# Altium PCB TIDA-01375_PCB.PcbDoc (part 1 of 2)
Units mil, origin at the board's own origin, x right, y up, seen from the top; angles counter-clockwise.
Board outline 3937.01 x 3149.61 mil, 2 copper layers (Top Layer, Bottom Layer), stack 62 mil thick; 52 components, 33 nets, 136 pads, 897 vias.
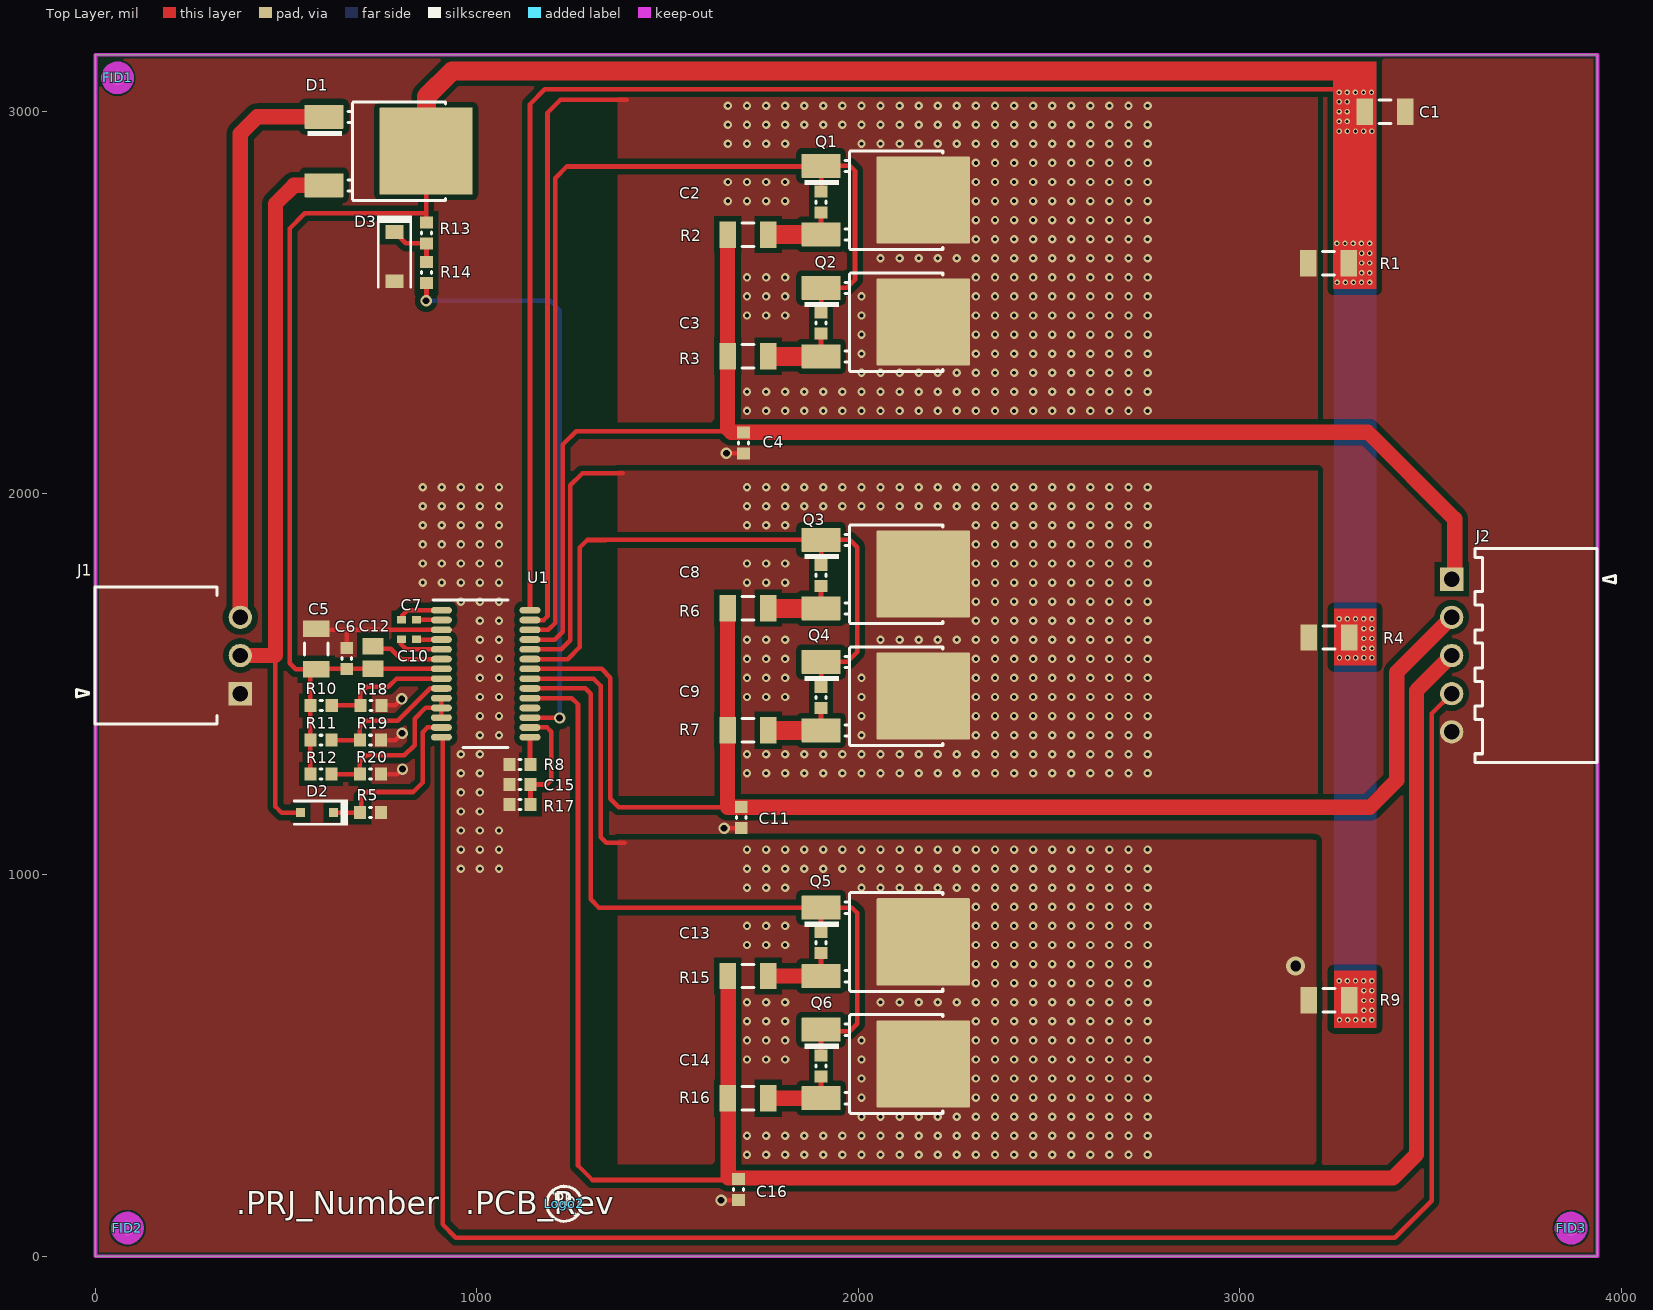
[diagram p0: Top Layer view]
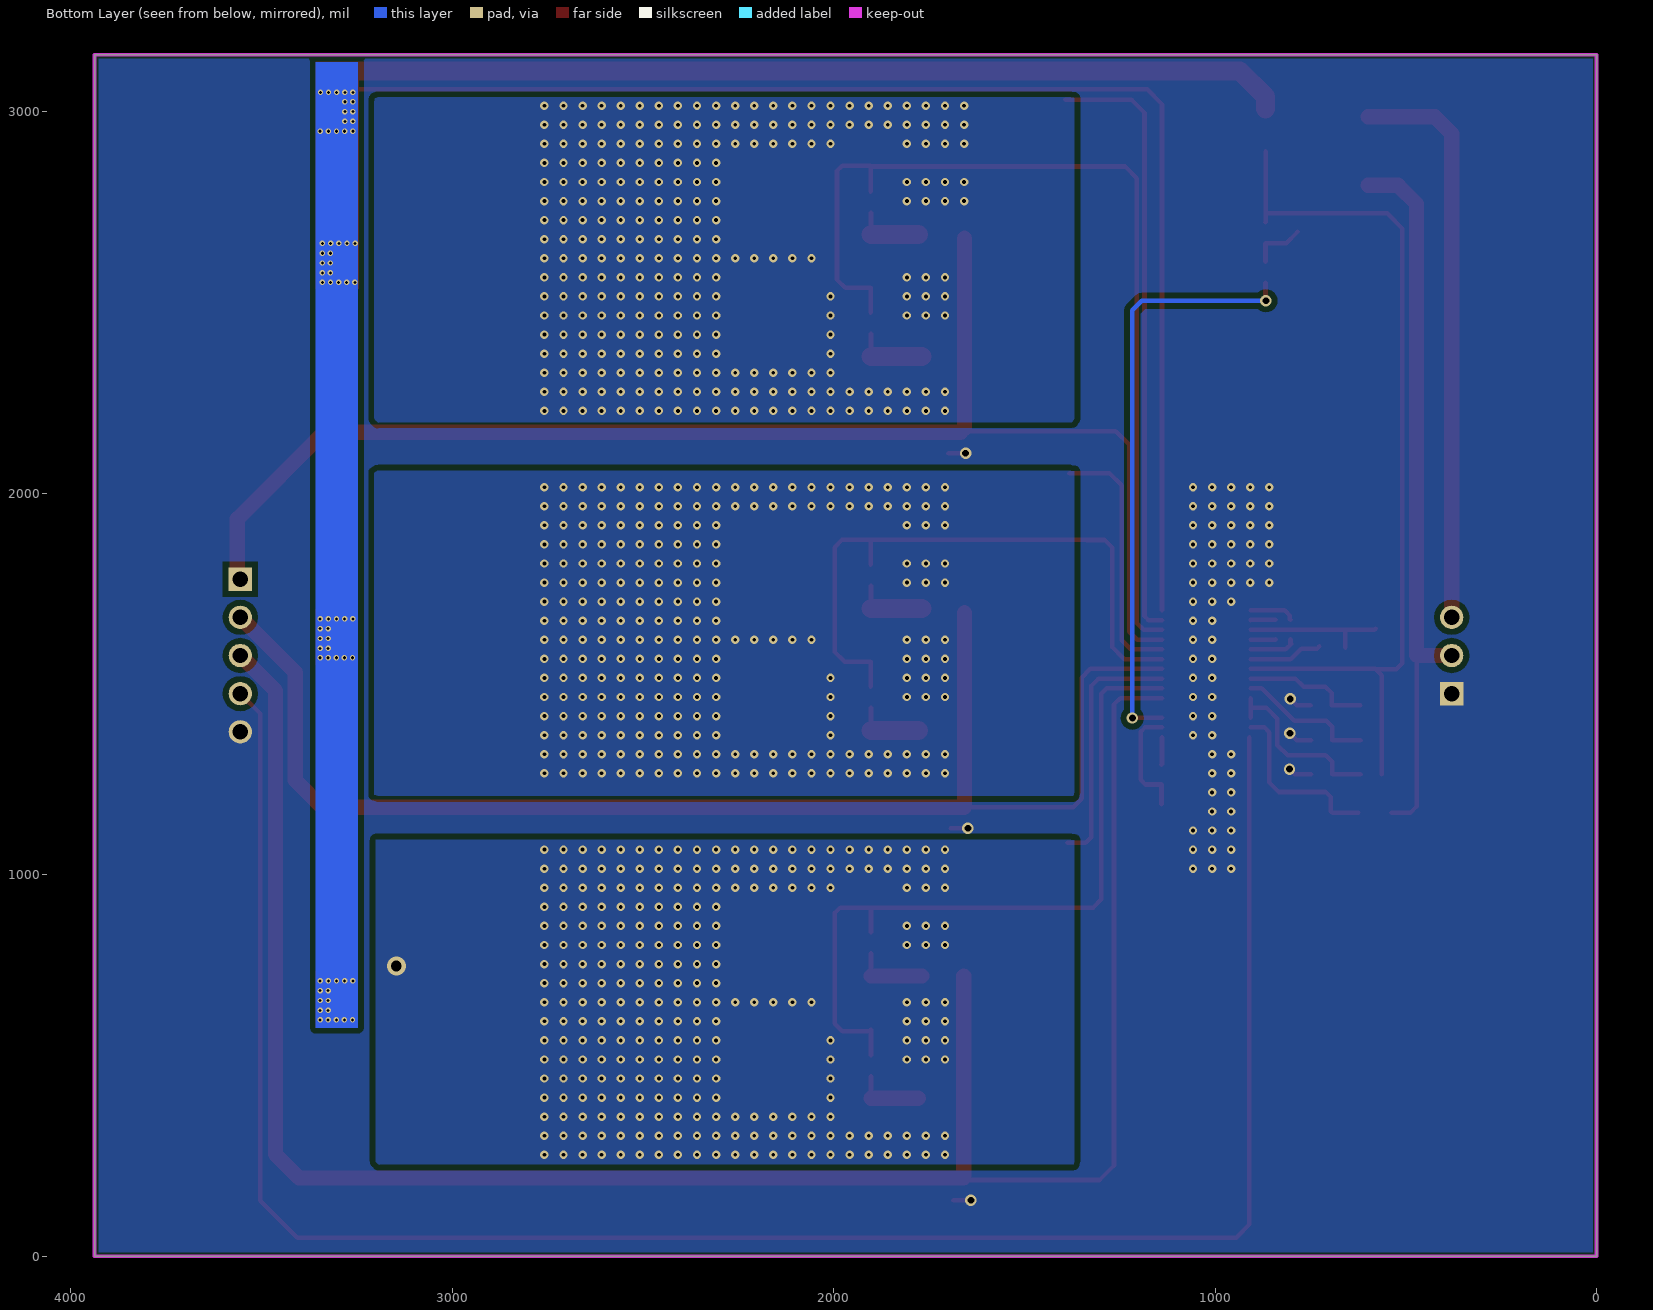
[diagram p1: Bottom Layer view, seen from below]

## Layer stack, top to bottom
Top Solder: solder mask 0.4, Solder Resist, Dk 3.5
Top Layer: signal copper 1.4
Dielectric1: core 59.2, FR-4, Dk 4.8
Bottom Layer: signal copper 1.4
Bottom Solder: solder mask 0.4, Solder Resist, Dk 3.5

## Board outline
0,0 3937.01,0 3937.01,3149.61 0,3149.61

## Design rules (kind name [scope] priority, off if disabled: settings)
AcuteAngle [All] p1: minimum=4.50000000000000E+0001 checktracksonly=FALSE
AssemblyTestPointUsage [All] p1: valid=2
Clearance Clearance_Keepouts [((IsTrack Or IsArc) And Not InPoly) And IsFree and IsKeepOut vs ((IsTrack Or IsArc) And Not InPoly) And IsFree and IsKeepOut] p1: gap=0 ignorepadtopadclearanceinfootprint=FALSE
Clearance Clearance_BoardEdge_MountingHoles [OnCopper and InComponentClass('Mounting Holes') vs IsKeepOut] p2: gap=40 ignorepadtopadclearanceinfootprint=FALSE except(0: Arc-Hole Track-Hole SMDPad-Hole THPad-Hole Via-Hole Fill-Hole Poly-Hole Region-Hole Text-Hole)
Clearance Clearance_BoardEdge_Poly [OnCopper and InPoly vs IsKeepOut] p3: gap=5 ignorepadtopadclearanceinfootprint=FALSE except(0: Arc-Hole Track-Hole SMDPad-Hole THPad-Hole Via-Hole Fill-Hole Poly-Hole Region-Hole Text-Hole)
Clearance Clearance_BoardEdge [OnCopper and Not InComponentClass('Logo') and not InComponentClass('FiducialMark') and not InRegion(1000,500,4000,800) and Not IsKeepout vs IsKeepOut] p4: gap=5 ignorepadtopadclearanceinfootprint=FALSE except(0: Arc-Hole Track-Hole SMDPad-Hole THPad-Hole Via-Hole Fill-Hole Poly-Hole Region-Hole Text-Hole)
Clearance Clearance_Poly [InPolygon] p5: gap=15 ignorepadtopadclearanceinfootprint=FALSE except(0: Arc-Hole Track-Hole SMDPad-Hole THPad-Hole Via-Hole Fill-Hole Poly-Hole Region-Hole Text-Hole)
Clearance [All] p6: gap=7.87 ignorepadtopadclearanceinfootprint=FALSE except(0: Arc-Hole Track-Hole SMDPad-Hole THPad-Hole Via-Hole Fill-Hole Poly-Hole Region-Hole Text-Hole)
ComponentClearance ComponentClearance_MountingHoles_FiducialMarks [InComponentClass('Mounting Holes') vs InComponentClass('FiducialMark')] p1: gap=50 collisioncheckmode=3 verticalgap=10 showdistances=FALSE
ComponentClearance ComponentClearance_Shunt [InComponentClass('Header') vs InComponentClass('Shunt')] p2: gap=0 collisioncheckmode=3 verticalgap=0 showdistances=FALSE
ComponentClearance ComponentClearance_Logo [InComponentClass('Logo')] p3: gap=50 collisioncheckmode=3 verticalgap=10 showdistances=FALSE
ComponentClearance ComponentClearance_ScrewToNut [(HasFootprint('NY PMS 440 0025 PH')) vs (HasFootprint('Keystone_1902C'))] p4: gap=5 collisioncheckmode=3 verticalgap=10 showdistances=FALSE
ComponentClearance ComponentClearance_MountingHoles [InComponentClass('Mounting Holes')] p5: gap=250 collisioncheckmode=3 verticalgap=100000 showdistances=FALSE
ComponentClearance ComponentClearance_SmallPassives [HasFootprint('0201*') or HasFootprint('0402*') or HasFootprint('0508') or HasFootprint('0603*') or HasFootprint('0612') or HasFootprint('0805*') or HasFootprint('0815*') or HasFootprint('0830*') or HasFootprint('1206*') or HasFootprint('1210*') or HasFootprint('1808*') or HasFootprint('1812*') or HasFootprint('1825*') or HasFootprint('2010*') or HasFootprint('2220*') or HasFootprint('2225*') or HasFootprint('2512*') or HasFootprint('2728*') or HasFootprint('3518*') vs HasFootprint('0201*') or HasFootprint('0402*') or HasFootprint('0508') or HasFootprint('0603*') or HasFootprint('0612') or HasFootprint('0805*') or HasFootprint('0815*') or HasFootprint('0830*') or HasFootprint('1206*') or HasFootprint('1210*') or HasFootprint('1808*') or HasFootprint('1812*') or HasFootprint('1825*') or HasFootprint('2010*') or HasFootprint('2220*') or HasFootprint('2225*') or HasFootprint('2512*') or HasFootprint('2728*') or HasFootprint('3518*')] p6: gap=5 collisioncheckmode=3 verticalgap=10 showdistances=FALSE
ComponentClearance ComponentClearance_THtoSMT [IsThruComponent vs IsSMTComponent] p7: gap=100 collisioncheckmode=3 verticalgap=30 showdistances=FALSE
ComponentClearance ComponentClearance_THtoTH [IsThruComponent vs IsThruComponent] p8: gap=118.11 collisioncheckmode=3 verticalgap=30 showdistances=FALSE
ComponentClearance [All] p9: gap=5 collisioncheckmode=3 verticalgap=10 showdistances=FALSE
DiffPairsRouting [All] p1: maxlimit=100 minlimit=10 mostfreqgap=10 toplayer_minwidth=15 toplayer_maxwidth=15 toplayer_prefwidth=15 bottomlayer_minwidth=15 bottomlayer_maxwidth=15 bottomlayer_prefwidth=15 maxuncoupledlength=1000
FabricationTestPointUsage TestPointUsage [All] p1: valid=2 allowmultiple=FALSE
FabricationTestpoint Testpoint [All] p1: side=3 testpointundercomponent=TRUE minsize=40 maxsize=100 preferedsize=60 minholesize=0 maxholesize=40 preferedholesize=32 testpointgrid=1 allowsidetop=TRUE allowsidebottom=TRUE usegrid=TRUE gridtolerance=0.01
FanoutControl Fanout_LCC [IsLCC] p1: bgadir=Out bgaviamode=Centered fanoutstyle=Auto fanoutdirection=Alternating viagrid=1 // Fanout_LCC (Default Rule)
FanoutControl Fanout_BGA [IsBGA] p2: bgadir=Out bgaviamode=Centered fanoutstyle=Auto fanoutdirection=Alternating viagrid=1 // Fanout_BGA (Default Rule)
FanoutControl Fanout_Default [All] p4: bgadir=Out bgaviamode=Centered fanoutstyle=Auto fanoutdirection=Alternating viagrid=1 // Fanout_Default (Default Rule)
FanoutControl Fanout_Small [(CompPinCount < 5)] p5: bgadir=Out bgaviamode=Centered fanoutstyle=Auto fanoutdirection=OutThenIn viagrid=1 // Fanout_Small (Default Rule)
HoleSize [All] p1: absolutevalues=TRUE maxlimit=251 minlimit=8 maxpercent=80.000 minpercent=20.000
MinimumAnnularRing MinimumAnnularRing_ThermalPadVias [IsVia and InAnyComponent] p1: minimumring=5.91
MinimumAnnularRing [All] p2: minimumring=9
MinimumSolderMaskSliver MinimumSolderMaskSliver_Logo [InComponentClass('Logo') vs InComponentClass('Logo')] p1: minsoldermaskwidth=0.7
MinimumSolderMaskSliver [All] p2: minsoldermaskwidth=3.94
PlaneConnect [All] p1: planeconnectstyle=Direct reliefexpansion=10 reliefentries=4 reliefconductorwidth=10 reliefairgap=10
PolygonConnect [All] p1: connectstyle=Direct reliefconductorwidth=10 reliefentries=4 polygonreliefangle="90 Angle" airgapwidth=10
RoutingVias ThermalPadVias [IsVia and InAnyComponent] p1: holewidth=7.87 width=19.68 viastyle="Through Hole" minholewidth=7.87 minwidth=19.68 maxholewidth=12.99 maxwidth=23.62
RoutingVias [All] p2: holewidth=16 width=34 viastyle="Through Hole" minholewidth=7.87 minwidth=26 maxholewidth=40 maxwidth=65
SilkToBoardRegionClearance [Not ((IsComment or IsDesignator) And (Hide <> 'False')) and not InRegion(1000,500,4000,800)] p1:
SilkToSilkClearance SilkToSilkClearance_Pb-FreeLogo [(HasFootprint('Pb-Free_Overlay_Medium') OR HasFootprint('Pb-Free_Overlay_Small')) vs (HasFootprint('Pb-Free_Overlay_Medium') OR HasFootprint('Pb-Free_Overlay_Small'))] p1: silktosilkclearance=0
SilkToSilkClearance [All] p2: silktosilkclearance=4
SilkToSolderMaskClearance SilkToComonentPadClearance [IsPad and InAnycomponent] p1: minsilkscreentomaskgap=5 clearancetoexposedcopper=TRUE
SilkToSolderMaskClearance "Silk to Solder Mask Opening" [All] p2: minsilkscreentomaskgap=4 clearancetoexposedcopper=FALSE
SolderMaskExpansion [All] p1: expansion=1.97
Width [All] p1: maxlimit=100 minlimit=6 preferedwidth=10 checkconnectedcopper=TRUE
15 further rules are at their usual default settings.

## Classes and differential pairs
component class TIDA-01375_Hardware: FID1 FID2 FID3 Logo2
component class FiducialMark: FID1 FID2 FID3
component class TIDA-01375_Main: C1 C2 C3 C4 C5 C6 C7 C8 C9 C10 C11 C12 C13 C14 C15 C16 D1 D2 D3 J1 J2 Q1 Q2 Q3 Q4 Q5 Q6 R1 R2 R3 R4 R5 R6 R7 R8 R9 R10 R11 R12 R13 R14 R15 R16 R17 R18 R19 R20 U1

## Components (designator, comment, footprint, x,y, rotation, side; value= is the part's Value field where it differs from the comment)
C1 "UMK316B7225KL-T" 1206L 3380,3000 r0 top value=2.2uF
C2 "GRM188R71E472KA01D" 0603L 1902,2763 r270 top value=4700pF
C3 "GRM188R71E472KA01D" 0603L 1902,2446 r90 top value=4700pF
C4 "06031C103JAT2A" 0603L 1699,2132 r270 top value=0.01uF
C5 "UMK316B7225KL-T" 1206L 579,1591.81 r90 top value=2.2uF
C6 "06031C103JAT2A" 0603L 659,1567.31 r90 top value=0.01uF
C7 "GCM155R71H103KA55D" 0402L 822.06,1668 r0 top value=0.01uF
C8 "GRM188R71E472KA01D" 0603L 1902,1785 r270 top value=4700pF
C9 "GRM188R71E472KA01D" 0603L 1902,1465 r90 top value=4700pF
C10 "GCM155R71H103KA55D" 0402L 822.06,1616.83 r0 top value=0.01uF
C11 "06031C103JAT2A" 0603L 1693,1150 r270 top value=0.01uF
C12 "C0805C154K5RACTU" 0805L 727.18,1569.17 r270 top value=0.15uF
C13 "GRM188R71E472KA01D" 0603L 1902,822 r270 top value=4700pF
C14 "GRM188R71E472KA01D" 0603L 1902,499 r90 top value=4700pF
C15 "GRM188R71C683KA01D" 0603L 1113,1236.71 r180 top value=0.068uF
C16 "06031C103JAT2A" 0603L 1686,175 r270 top value=0.01uF
D1 "RB095B-60TL" DPAK 733,2897 r0 top value=60V
D2 "BAS16J,135" SOD-323F 581,1163 r180 top value=100V
D3 "BZT52B16" SOD-123 784,2620.53 r270 top value=16V
FID1 "Fiducial" Fiducial10-20 58,3089 r0 top
FID2 "Fiducial" Fiducial10-20 84,74 r0 top
FID3 "Fiducial" Fiducial10-20 3868,74 r0 top
J1 "IPL1-103-01-F-S-RA-K" Samtec_IPL1-103-01-x-S-RA-K 380,1574.8 r90 top
J2 "IPL1-105-01-L-S-RA-K" Samtec_IPL1-105-01-x-S-RA-K 3555,1574.8 r270 top
Logo2 "Pb-Free Symbol" Pb-Free_Overlay_Small 1229.2,137.7 r0 top
Q1 "NTD3055-150T4G" DPAK 2036.06,2768.56 r0 top value=60V
Q2 "NTD3055-150T4G" DPAK 2036.06,2448.57 r0 top value=60V
Q3 "NTD3055-150T4G" DPAK 2036.06,1788.24 r0 top value=60V
Q4 "NTD3055-150T4G" DPAK 2036.06,1468.24 r0 top value=60V
Q5 "NTD3055-150T4G" DPAK 2036.06,824.39 r0 top value=60V
Q6 "NTD3055-150T4G" DPAK 2036.06,504.39 r0 top value=60V
R1 "CSR1206FK1R00" 1206L 3232,2603 r0 top value=1.00
R2 "CSR1206FK1R00" 1206L 1711,2678 r0 top value=1.00
R3 "CSR1206FK1R00" 1206L 1711,2359 r0 top value=1.00
R4 "CSR1206FK1R00" 1206L 3233,1622 r0 top value=1.00
R5 "CRCW060320K0FKEA" 0603L 721,1163 r180 top value=20.0k
R6 "CSR1206FK1R00" 1206L 1711,1699 r0 top value=1.00
R7 "CSR1206FK1R00" 1206L 1711,1379 r0 top value=1.00
R8 "RT0603BRD078K06L" 0603L 1113,1289 r0 top value=8.06k
R9 "CSR1206FK1R00" 1206L 3233,671 r0 top value=1.00
R10 "CRCW0603124KFKEA" 0603L 592,1444 r180 top value=124k
R11 "CRCW0603182KFKEA" 0603L 591,1353 r180 top value=182k
R12 "CRCW060375K0FKEA" 0603L 591,1264 r180 top value=75.0k
R13 "CRCW06031K00FKEA" 0603L 868,2682.53 r90 top value=1.00k
R14 "DNP" 0603L 868,2579.1 r270 top value=0
R15 "CSR1206FK1R00" 1206L 1711,734.47 r0 top value=1.00
R16 "CSR1206FK1R00" 1206L 1711,414.47 r0 top value=1.00
R17 "RT0603DRE0755K6L" 0603L 1113,1184.43 r0 top value=55.6k
R18 "CRCW060320K0FKEA" 0603L 722,1444 r180 top value=20.0k
R19 "CRCW060320K0FKEA" 0603L 721,1353 r180 top value=20.0k
R20 "CRCW060320K0FKEA" 0603L 721,1264 r180 top value=20.0k
U1 "TPS92830QPWRQ1" PW0028A_N 1023,1527 r0 top

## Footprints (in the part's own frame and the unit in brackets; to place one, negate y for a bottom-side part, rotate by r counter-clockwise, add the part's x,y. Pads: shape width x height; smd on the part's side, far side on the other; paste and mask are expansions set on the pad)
0402L [mm] "0402 from SM-752 data"
  rect 0.6x0.5 smd: 1(-0.5,0) 2(0.5,0)
  body extent -0.55,-0.3 0.55,0.3, height 0.6
0603L [mm] "0603 from SM-752 data"
  rect 0.8x0.85 smd: 1(-0.7,0) 2(0.7,0)
  silkscreen extent -0.07,-0.33 0.07,0.33, body extent -0.87,-0.47 0.87,0.47, height 1
0805L [mm] "0805 from SM-752 data"
  rect 1.1x1.4 smd: 1(-0.75,0) 2(0.75,0)
  body extent -1.1,-0.72 1.1,0.72, height 1.45
1206L [mm] "1206 from SM-752 data"
  rect 1.1x1.75 smd: 1(-1.35,0) 2(1.35,0)
  silkscreen extent -0.4,-0.77 0.4,0.77, body extent -1.7,-0.9 1.7,0.9, height 1.35
DPAK [mm] "D-PAK, 3-Pads, Body 6.22x6.73mm (max), TO-252AA using nominal STEP model"
  rrect6% 2.6x1.6 smd: 1(-3.4,2.28) 3(-3.4,-2.28)
  rrect2% 6.2x5.8 smd paste-2.9: 4(3.4,0)
  silkscreen extent -4.5,-3.3 4.7,3.28, body extent -3.86,-3.29 5.84,3.29, height 2.48
Fiducial10-20 [mm]
  round 1 smd mask+0.5: 1(0,0)
  Top Layer keep-out circle w1.178: c0,0 r0.5
Pb-Free_Overlay_Small [mil]
  silkscreen extent -46,-46 46,46
PW0028A_N [mm] "TSOP, 28-Leads, Body 9.7x4.4mm, Pitch 0.65mm, IPC Medium Density"
  oval 1.4x0.45 smd: 1(-2.95,4.225) 2(-2.95,3.575) 3(-2.95,2.925) 4(-2.95,2.275) 5(-2.95,1.625) 6(-2.95,0.975) 7(-2.95,0.325) 8(-2.95,-0.325) 9(-2.95,-0.975) 10(-2.95,-1.625) 11(-2.95,-2.275) 12(-2.95,-2.925) 13(-2.95,-3.575) 14(-2.95,-4.225) 15(2.95,-4.225) 16(2.95,-3.575) 17(2.95,-2.925) 18(2.95,-2.275) 19(2.95,-1.625) 20(2.95,-0.975) 21(2.95,-0.325) 22(2.95,0.325) 23(2.95,0.975) 24(2.95,1.625) 25(2.95,2.275) 26(2.95,2.925) 27(2.95,3.575) 28(2.95,4.225)
  silkscreen extent -3.5,-4.9 1.5,4.9, body extent -3.21,-4.85 3.21,4.85, height 1
Samtec_IPL1-103-01-x-S-RA-K [mm] "Header(Shrouded), 2.54mm, 3x1, R/A, TH"
  rect 1.55x1.55 hole 1.02: 1(-2.54,0)
  round 1.55 hole 1.02: 2(0,0) 3(2.54,0)
  silkscreen extent -4.57,1.54 4.57,10.9, body extent -4.57,-0.3 4.57,9.67, height 6.6
Samtec_IPL1-105-01-x-S-RA-K [mm] "Header(Shrouded), 2.54mm, 5x1, R/A, TH"
  rect 1.55x1.55 hole 1.02: 1(-5.08,0)
  round 1.55 hole 1.02: 2(-2.54,0) 3(0,0) 4(2.54,0) 5(5.08,0)
  silkscreen extent -7.11,1.54 7.11,10.9, body extent -7.11,-0.3 7.11,9.67, height 6.6
SOD-123 [mm] "On Semi recommended land pattern"
  rect 0.915x1.22 smd: 1(-1.637,0) 2(1.637,0)
  silkscreen extent -2.74,-1.17 2.03,1.17, body extent -1.93,-0.9 1.93,0.9, height 1.35
SOD-323F [mm] "NXP recommended land pattern"
  rect 0.6x0.6 smd paste-0.05: 1(-1.1,0) 2(1.1,0)
  silkscreen extent -2.06,-0.86 1.53,0.86, body extent -1.35,-0.67 1.35,0.68, height 0.79

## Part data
C1 C5: "CAP, CERM, 2.2 µF, 50 V, +/- 10%, X7R, 1206", Cap_Case=1206, Manufacturer="Taiyo Yuden", Supplier Part Number 1=587-2911-1-ND, TempCo=X7R, Tolerance_%=10, Value1=Unknown, Value2=50V, ValueDisplayed=2.2µF
C2 C3 C8 C9 C13 C14: "CAP, CERM, 4700 pF, 25 V, +/- 10%, X7R, 0603", Cap_Case=0603, Manufacturer=MuRata, Supplier Part Number 1=81-GRM39X472K25D, TempCo=X7R, Tolerance_%=10, Value1=Unknown, Value2=25V, ValueDisplayed=4700pF
C4 C11 C16: "CAP, CERM, 0.01 µF, 100 V, +/- 5%, X7R, 0603", Cap_Case=0603, Manufacturer=AVX, Supplier Part Number 1=478-3700-1-ND, TempCo=X7R, Tolerance_%=5, Value1="0.098 ohm", Value2=100V, ValueDisplayed=10nF
C6: "CAP, CERM, 0.01 µF, 100 V, +/- 5%, X7R, 0603", Cap_Case=0603, Manufacturer=AVX, Supplier Part Number 1=478-3700-1-ND, TempCo=X7R, Tolerance_%=5, Value1="0.098 ohm", Value2=100V, ValueDisplayed=0.01µF
C7 C10: "CAP, CERM, 0.01 µF, 50 V, +/- 10%, C0G/NP0, 0402", Cap_Case=0402, Manufacturer=MuRata, Supplier Part Number 1=490-4762-1-ND, TempCo=C0G/NP0, Tolerance_%=10, Value1=Unknown, Value2=50V, ValueDisplayed=0.01µF
C12: "CAP, CERM, 0.15 µF, 50 V, +/- 10%, X7R, 0805", Cap_Case=0805, Manufacturer=Kemet, Supplier Part Number 1=399-3489-1-ND, TempCo=X7R, Tolerance_%=10, Value1="0.054 ohm", Value2=50V, ValueDisplayed=0.15µF
C15: "CAP, CERM, 0.068 µF, 16 V, +/- 10%, X7R, 0603", Cap_Case=0603, Manufacturer=MuRata, Supplier Part Number 1=490-1531-1-ND, TempCo=X7R, Tolerance_%=10, Value1=Unknown, Value2=16V, ValueDisplayed=0.068µF
D1: "Diode, Schottky, 60 V, 3 A, DPAK", Manufacturer=Rohm, Supplier Part Number 1=RB095B-60TLCT-ND, Value1=3A, Value2=0.58V
D2: "Diode, Switching, 100 V, 0.25 A, SOD-323F", Manufacturer="NXP Semiconductor", Supplier Part Number 1=568-5996-1-ND, Value1=0.25A, Value2=V
D3: library part BZT52B16-HE3-08, "Diode, Zener, 16 V, 410 mW, AEC-Q101, SOD-123", Manufacturer=Vishay-Semiconductor, Power_W=0.41, Supplier Part Number 1=BZT52B16-HE3-08-ND, Value1=0.41W
FID1 FID2 FID3: "Fiducial mark.  There is nothing to buy or mount.", Manufacturer=N/A
J1: "Header(Shrouded), 2.54mm, 3x1, Gold, R/A, TH", Color=Natural, Current_A=3.8, Manufacturer=Samtec, Voltage_V=954
J2: "Header(Shrouded), 2.54mm, 5x1, Gold, R/A, TH", Color=Natural, Current_A=3.8, Manufacturer=Samtec, Supplier Part Number 1=IPL1-105-01-L-S-RA-K-ND, Voltage_V=954
Logo2: library part Pb-Free
Q1 Q2 Q3 Q4 Q5 Q6: "MOSFET, N-CH, 60 V, 9 A, AEC-Q101, DPAK", Alternate Manufacturer=None, Manufacturer="ON Semiconductor", Supplier Part Number 1=NTD3055-150T4GOSCT-ND, Value1="? ohm", Value2="7.1 nC"
R1 R2 R3 R4 R6 R7 R9 R15 R16: "RES, 1.00, 1%, 0.5 W, 1206", Manufacturer="Stackpole Electronics Inc", Power_W=0.5, Supplier Part Number 1=CSR1206FK1R00CT-ND, TempCo="100 ppm/C", Tolerance_%=1, Value1=1%, Value2=0.5W, Value_Code=1R00, ValueDisplayed=1.00
R5 R18 R19 R20: "RES, 20.0 k, 1%, 0.1 W, 0603", Manufacturer=Vishay-Dale, Power_W=0.1, Supplier Part Number 1=541-20.0KHCT-ND, TempCo="100 ppm/C", Tolerance_%=1, Value1=1%, Value2=0.1W, Value_Code=20k0, ValueDisplayed=20.0k
R8: "RES, 8.06 k, 0.1%, 0.1 W, 0603", Manufacturer="Yageo America", Power_W=0.1, TempCo="25 ppm/C", Value1=0.1%, Value2=0.1W, Value_Code=8k06, ValueDisplayed=8.06k
R10: library part CMP-0022026-3, "RES, 124 k, 1%, 0.1 W, 0603", Manufacturer=Vishay-Dale, Power_W=100mW, Supplier Part Number 1=541-124KHCT-ND, TempCo="100 ppm/C", Tolerance_%=1%, Value2=0.1W, Value_Code=124k
R11: library part CMP-0022093-3, "RES, 182 k, 1%, 0.1 W, 0603", Manufacturer=Vishay-Dale, Power_W=100mW, Supplier Part Number 1=541-182KHCT-ND, TempCo="100 ppm/C", Tolerance_%=1%, Value2=0.1W, Value_Code=182k
R12: library part CMP-0022589-3, "RES, 75.0 k, 1%, 0.1 W, 0603", Manufacturer=Vishay-Dale, Power_W=100mW, Supplier Part Number 1=541-75.0KHCT-ND, TempCo="100 ppm/C", Tolerance_%=1%, Value2=0.1W, Value_Code=75k0, ValueDisplayed=75.0k
R13: "RES, 1.00 k, 1%, 0.1 W, 0603", Manufacturer=Vishay-Dale, Power_W=0.1, Supplier Part Number 1=541-1.00KHCT-ND, TempCo="100 ppm/C", Tolerance_%=1, Value1=1%, Value2=0.1W, Value_Code=1k00, ValueDisplayed=1.00k
R14: library part CRCW06030000Z0EA, "RES, 0, 5%, 0.1 W, 0603", Manufacturer=Vishay-Dale, Power_W=0.1, Supplier Part Number 1=541-0.0GCT-ND, TempCo="200 ppm/C", Tolerance_%=5, Value1=5%, Value2=0.1W, Value_Code=0000, ValueDisplayed=0
R17: "RES, 55.6 k, 0.5%, 0.1 W, 0603", Manufacturer="Yageo America", Power_W=0.1, TempCo="50 ppm/C", Tolerance_%=0.5, Value1=0.5%, Value2=0.1W, Value_Code=55k6, ValueDisplayed=55.6k
U1: "3-CH High Current Linear LED Controller with Diagnostics and One-Fail-All-Fail Fault Bus, PW0028A", Alternate Manufacturer="Texas Instruments"

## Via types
v1: diameter 22, hole 10, Top Layer to Bottom Layer, 824 vias
v2: diameter 14, hole 8, Top Layer to Bottom Layer, 64 vias
v3: diameter 30, hole 18, Top Layer to Bottom Layer, 8 vias
v4: diameter 50, hole 28, Top Layer to Bottom Layer, 1 vias

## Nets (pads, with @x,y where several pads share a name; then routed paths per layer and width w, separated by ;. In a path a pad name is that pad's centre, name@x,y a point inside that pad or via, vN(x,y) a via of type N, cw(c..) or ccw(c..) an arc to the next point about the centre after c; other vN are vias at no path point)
/FAULT: R14.2 U1.17 | length 1554.8
  Top Layer w12: v3(867,2504.53) 868,2505.53 R14.2@868,2551.54 ; U1.17@1139.14,1411.84 1216.16,1411.84 v3(1217,1411)
  Bottom Layer w12: v3(867,2504.53) 1192.47,2504.53 1217,2480 v3(1217,1411)
DERATE: R11.1 R19.2 U1.9 | length 365.2
  Top Layer w12: R11.1@618.56,1353 R19.2@693.44,1353 693.44,1388.44 709,1404 793,1404 877.61,1488.61 U1.9@906.86,1488.61
DIAGEN: R10.1 R18.2 U1.8 | length 335.4
  Top Layer w12: R10.1@619.56,1444 R18.2@694.44,1444 694.44,1476.44 711,1493 768,1493 789.2,1514.2 U1.8@906.86,1514.2
DRL: D1.3 D2.2 J1.2 | length 1891.4
  Top Layer w12: 472,1574.8 472,1179 488,1163 D2.2@537.69,1163
  Top Layer w40: J1.2@380,1574.8 472,1574.8 472,2759 520.24,2807.24 D1.3@599.14,2807.24
FD: D2.1 R5.2 U1.13 | length 474.3
  Top Layer w12: D2.1@624.31,1163 R5.2@693.44,1163 697,1166.56 697,1204 710,1217 833,1217 858,1242 858,1374 870.25,1386.25 U1.13@906.86,1386.25
GND: C1.2 C4.2 C5.2 C6.2 C11.2 C15.2 C16.2 D3.2 J1.1 J2.5 R5.1 R8.1 R17.1 R18.1 R19.1 R20.1 U1.3 | length 697.5
  Top Layer w12: C5.2@579,1644.96 581.8,1642.16 659,1642.16 ; C6.2@659,1594.87 659,1642.16 ; R20.1@748.56,1264 792,1264 v3(805,1277) ; R19.1@748.56,1353 786,1353 v3(804,1371) ; R18.1@749.56,1444 786,1444 v3(803,1461) ; U1.3@906.86,1642.16 659,1642.16 ; v3@1640.44,147.44 C16.2@1686,147.44 ; v3(1648,1122) 1648.44,1122.44 C11.2@1693,1122.44 ; v3(1654,2105) 1654.56,2104.44 C4.2@1699,2104.44
  other v1: 958,1016 1008,1016 1058,1016 958,1066 1008,1066 1058,1066 958,1116 1008,1116 1058,1116 958,1166 1008,1166 958,1216 1008,1216 958,1266 1008,1266 958,1316 1008,1316 1008,1366 1058,1366 1008,1416 1058,1416 1008,1466 1058,1466 1008,1516 1058,1516 1008,1566 1058,1566 1008,1616 1058,1616 1008,1666 1058,1666 958,1716 1008,1716 1058,1716 858,1766 908,1766 958,1766 1008,1766 1058,1766 858,1816 908,1816 958,1816 1008,1816 1058,1816 858,1866 908,1866 958,1866 1008,1866 1058,1866 858,1916 908,1916 958,1916 1008,1916 1058,1916 858,1966 908,1966 958,1966 1008,1966 1058,1966 858,2016 908,2016 958,2016 1008,2016 1058,2016
  other v3: 1640,147
ICTRL: J2.4 U1.14 | length 5274.7
  Top Layer w12: U1.14@910,1360.66 910,84 945,49 3406,49 3503,146 3503,1422.8 J2.4@3555,1474.8
NetC2_1: C2.1 C3.2 Q1.1 Q2.1 U1.26 | length 2559.1
  Top Layer w12: U1.26@1139.14,1642.16 1187.16,1642.16 1205,1660 1205,2826 1235.56,2856.56 1900.43,2856.56 Q1.1@1902.2,2858.33 ; C3.2@1902.2,2473.76 Q2.1@1902.2,2538.33 1969.33,2538.33 1991,2560 1991,2845 1977.67,2858.33 Q1.1@1902.2,2858.33 ; C2.1@1902.2,2790.76 Q1.1@1902.2,2858.33
NetC2_2: C2.2 Q1.3 R2.2 | length 180.7
  Top Layer w12: Q1.3@1902,2679 C2.2@1902,2735.44
  Top Layer w50: R2.2@1777.91,2678.8 Q1.3@1902.2,2678.8
NetC3_1: C3.1 Q2.3 R3.2 | length 193.6
  Top Layer w12: Q2.3@1902,2359 C3.1@1902,2418.44
  Top Layer w50: R3.2@1768.09,2358.8 Q2.3@1902.2,2358.8
NetC4_1: C4.1 J2.1 R2.1 R3.1 U1.25 | length 3684.5
  Top Layer w12: U1.25@1139.14,1616.57 1204.57,1616.57 1224.87,1636.87 1224.87,2127.87 1260,2163 1647.75,2163
  Top Layer w40: R2.1@1657,2668.75 1657,2170 1667,2160 3336,2160 3563,1933 J2.1@3563,1774
NetC7_1: C7.1 U1.1 | length 120.7
  Top Layer w12: C7.1@802.38,1668 804.34,1669.97 804.34,1679.79 817.89,1693.34 U1.1@906.86,1693.34
NetC7_2: C7.2 U1.2 | length 65.2
  Top Layer w12: C7.2@841.75,1668 906.61,1668 U1.2@906.86,1667.75
NetC8_1: C8.1 C9.2 Q3.1 Q4.1 U1.23 | length 1659.2
  Top Layer w12: U1.23@1139.14,1565.39 1238.39,1565.39 1270,1597 1270,1858 1289.56,1877.56 1338,1877.56 1338.45,1878.01 Q3.1@1902.2,1878.01 ; C9.2@1902.2,1492.76 Q4.1@1902.2,1558.01 1971.01,1558.01 1997,1584 1997,1859 1977.99,1878.01 Q3.1@1902.2,1878.01 ; C8.1@1902.2,1812.76 Q3.1@1902.2,1878.01
NetC8_2: C8.2 Q3.3 R6.2 | length 192.9
  Top Layer w12: Q3.3@1902,1698.68 C8.2@1902,1757.44
  Top Layer w50: R6.2@1768.09,1698.48 Q3.3@1902.2,1698.48
NetC9_1: C9.1 Q4.3 R7.2 | length 183.1
  Top Layer w12: Q4.3@1902,1378.68 C9.1@1902,1437.44
  Top Layer w50: R7.2@1777.91,1378.48 Q4.3@1902.2,1378.48
NetC10_1: C10.1 U1.5 | length 124.9
  Top Layer w12: C10.1@802.38,1616.83 802.38,1606.99 800.41,1605.02 814.45,1590.98 U1.5@906.86,1590.98
NetC10_2: C10.2 U1.4 | length 65.2
  Top Layer w12: C10.2@841.75,1616.83 842.01,1616.57 U1.4@906.86,1616.57
NetC11_1: C11.1 J2.2 R6.1 R7.1 U1.22 | length 3622.9
  Top Layer w12: U1.22@1139.14,1539.8 1327.2,1539.8 1350,1517 1350,1199 1372,1177 1645,1177
  Top Layer w40: R6.1@1657,1687 1657,1177 3341,1177 3411,1247 3411,1530.8 J2.2@3555,1674.8
NetC12_1: C12.1 U1.6 | length 193.5
  Top Layer w12: C12.1@727.18,1598.7 732.88,1593 774,1593 801.61,1565.39 U1.6@906.86,1565.39
NetC13_1: C13.1 C14.2 Q5.1 Q6.1 U1.20 | length 1944
  Top Layer w12: U1.20@1139.14,1488.61 1284.39,1488.61 1298,1475 1298,936 1319.84,914.16 Q5.1@1902.2,914.16 1982.84,914.16 1997,900 1997,610 1977,590 1906.36,590 Q6.1@1902.2,594.16 ; C14.2@1902,526.56 Q6.1@1902,593.96 ; C13.1@1902,849.56 Q5.1@1902,913.96
NetC13_2: C13.2 Q5.3 R15.2 | length 193.7
  Top Layer w12: Q5.3@1902,734.83 C13.2@1902,794.44
  Top Layer w40: R15.2@1768.09,734.63 Q5.3@1902.2,734.63
NetC14_1: C14.1 Q6.3 R16.2 | length 180.9
  Top Layer w12: Q6.3@1902,414.83 C14.1@1902,471.44
  Top Layer w40: R16.2@1777.91,414.63 Q6.3@1902.2,414.63
NetC16_1: C16.1 J2.3 R15.1 R16.1 U1.19 | length 5471
  Top Layer w12: U1.19@1139.14,1463.02 1248.98,1463.02 1265,1447 1265,238 1303,200 1661,200 C16.1@1670,191
  Top Layer w40: R15.1@1659,734.47 1659,205 3401,205 3463,267 3463,1482.8 J2.3@3555,1574.8
NetD3_1: D3.1 R13.1 R14.1 | length 144.8
  Top Layer w12: D3.1@784,2685 814.03,2654.97 R13.1@868,2654.97 R14.1@868,2606.66
NetQ1_4: Q1.4 Q2.4 R1.1 U1.27 | length 1591.2
  Top Layer w12: U1.27@1139.14,1667.75 1174.75,1667.75 1185,1678 1185,2997 1219,3031 1393,3031
  other v1: 1708,2216 1758,2216 1808,2216 1858,2216 1908,2216 1958,2216 2008,2216 2058,2216 2108,2216 2158,2216 2208,2216 2258,2216 2308,2216 2358,2216 2408,2216 2458,2216 2508,2216 2558,2216 2608,2216 2658,2216 2708,2216 2758,2216 1708,2266 1758,2266 1808,2266 1858,2266 1908,2266 1958,2266 2008,2266 2058,2266 2108,2266 2158,2266 2208,2266 2258,2266 2308,2266 2358,2266 2408,2266 2458,2266 2508,2266 2558,2266 2608,2266 2658,2266 2708,2266 2758,2266 2008,2316 2058,2316 2108,2316 2158,2316 2208,2316 2258,2316 2308,2316 2358,2316 2408,2316 2458,2316 2508,2316 2558,2316 2608,2316 2658,2316 2708,2316 2758,2316 2008,2366 2308,2366 2358,2366 2408,2366 2458,2366 2508,2366 2558,2366 2608,2366 2658,2366 2708,2366 2758,2366 2008,2416 2308,2416 2358,2416 2408,2416 2458,2416 2508,2416 2558,2416 2608,2416 2658,2416 2708,2416 2758,2416 1708,2466 1758,2466 1808,2466 2008,2466 2308,2466 2358,2466 2408,2466 2458,2466 2508,2466 2558,2466 2608,2466 2658,2466 2708,2466 2758,2466 1708,2516 1758,2516 1808,2516 2008,2516 2308,2516 2358,2516 2408,2516 2458,2516 2508,2516 2558,2516 2608,2516 2658,2516 2708,2516 2758,2516 1708,2566 1758,2566 1808,2566 2308,2566 2358,2566 2408,2566 2458,2566 2508,2566 2558,2566 2608,2566 2658,2566 2708,2566 2758,2566 2058,2616 2108,2616 2158,2616 2208,2616 2258,2616 2308,2616 2358,2616 2408,2616 2458,2616 2508,2616 2558,2616 2608,2616 2658,2616 2708,2616 2758,2616 2308,2666 2358,2666 2408,2666 2458,2666 2508,2666 2558,2666 2608,2666 2658,2666 2708,2666 2758,2666 2308,2716 2358,2716 2408,2716 2458,2716 2508,2716 2558,2716 2608,2716 2658,2716 2708,2716 2758,2716 1658,2766 1708,2766 1758,2766 1808,2766 2308,2766 2358,2766 2408,2766 2458,2766 2508,2766 2558,2766 2608,2766 2658,2766 2708,2766 2758,2766 1658,2816 1708,2816 1758,2816 1808,2816 2308,2816 2358,2816 2408,2816 2458,2816 2508,2816 2558,2816 2608,2816 2658,2816 2708,2816 2758,2816 2308,2866 2358,2866 2408,2866 2458,2866 2508,2866 2558,2866 2608,2866 2658,2866 2708,2866 2758,2866 1658,2916 1708,2916 1758,2916 1808,2916 2008,2916 2058,2916 2108,2916 2158,2916 2208,2916 2258,2916 2308,2916 2358,2916 2408,2916 2458,2916 2508,2916 2558,2916 2608,2916 2658,2916 2708,2916 2758,2916 1658,2966 1708,2966 1758,2966 1808,2966 1858,2966 1908,2966 1958,2966 2008,2966 2058,2966 2108,2966 2158,2966 2208,2966 2258,2966 2308,2966 2358,2966 2408,2966 2458,2966 2508,2966 2558,2966 2608,2966 2658,2966 2708,2966 2758,2966 1658,3016 1708,3016 1758,3016 1808,3016 1858,3016 1908,3016 1958,3016 2008,3016 2058,3016 2108,3016 2158,3016 2208,3016 2258,3016 2308,3016 2358,3016 2408,3016 2458,3016 2508,3016 2558,3016 2608,3016 2658,3016 2708,3016 2758,3016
